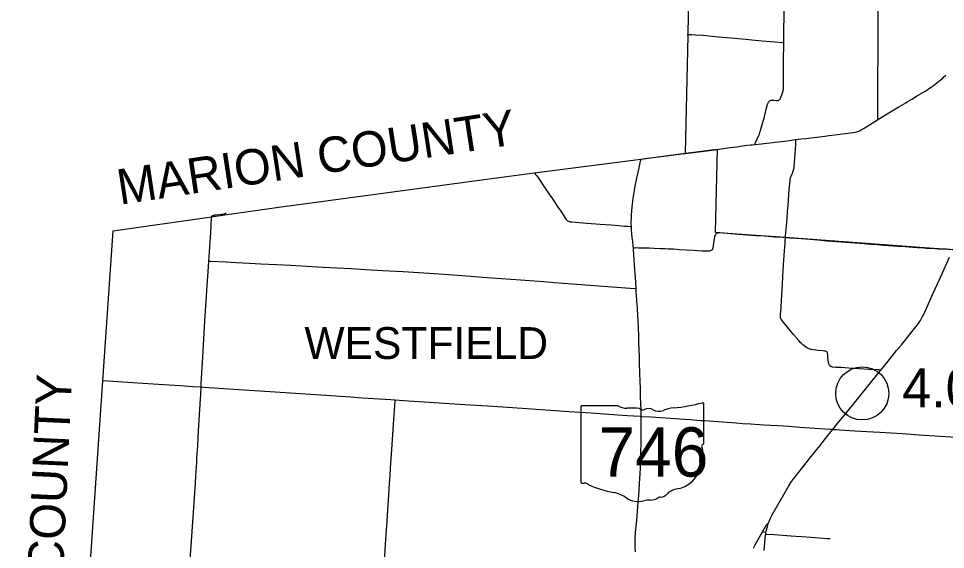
# Model space of a CAD drawing. Extents: x 1815539 to 1947826, y 273303 to 993194.
# Drawn here: x 1822046 to 1848246, y 896327 to 911339 of the extents above; entities that cross this region are included whole.
import ezdxf

# ---------------------------------------------------------------- set-up
doc = ezdxf.new("R2010")
doc.units = 0
for name, color, linetype in [('Default', 7, 'Continuous'), ('GM_X_Adjacent_County_Text', 7, 'Continuous'), ('GM_X_County', 7, 'Continuous'), ('GM_X_County_Road', 7, 'Continuous'), ('GM_X_State_Route', 7, 'Continuous'), ('GM_X_Township', 7, 'Continuous'), ('GM_X_Township_Road', 7, 'Continuous'), ('GM_X_Township_Text', 7, 'Continuous'), ('GM_X_US_Route', 7, 'Continuous'), ('SC_Shading3', 7, 'Continuous')]:
    doc.layers.add(name, color=color, linetype=linetype)

msp = doc.modelspace()

# ---------------------------------------------------------------- linework, layer by layer
at = {"layer": 'Default'}
msp.add_circle((1845895, 900740), 750, dxfattribs=at)
at = {"layer": 'GM_X_County'}
msp.add_lwpolyline([(1824025, 895167), (1824431, 901093), (1824723, 905333), (1827503, 905733), (1827940, 905796), (1829401, 906007), (1835631, 906848), (1836624, 906977), (1839634, 907367), (1840896, 907530), (1840970, 910855), (1841058, 916141)], dxfattribs=at)
at = {"layer": 'GM_X_County_Road'}
for points in [[(1846335, 908486), (1846602, 908646), (1846771, 908747), (1846926, 908839), (1847123, 908956), (1847166, 908980), (1847291, 909058), (1847431, 909144), (1847670, 909287), (1847753, 909339), (1847821, 909386), (1847904, 909446), (1848000, 909518), (1848094, 909595), (1848171, 909657), (1848195, 909678), (1848255, 909735)], [(1844020, 907915), (1844165, 907934), (1844311, 907951), (1844523, 907976), (1844767, 908006), (1844962, 908031), (1845271, 908070), (1845548, 908104), (1845645, 908118), (1845694, 908126), (1845742, 908138), (1845788, 908154), (1845818, 908167), (1845862, 908189), (1845946, 908240), (1846321, 908477), (1846335, 908486)], [(1842859, 907776), (1843042, 907796), (1843433, 907840), (1843709, 907876), (1844020, 907915)], [(1840900, 907526), (1841114, 907551), (1841268, 907569)], [(1841268, 907569), (1841276, 907570), (1841649, 907621), (1841792, 907640)], [(1841792, 907640), (1842086, 907679), (1842248, 907701), (1842361, 907716), (1842507, 907736), (1842637, 907754), (1842734, 907766), (1842783, 907770), (1842859, 907776)], [(1839641, 907367), (1839743, 907381), (1840149, 907433), (1840782, 907511), (1840900, 907526)], [(1836640, 906953), (1836662, 906929), (1836693, 906891), (1836740, 906824), (1836905, 906580), (1837062, 906349), (1837146, 906228), (1837275, 906038), (1837375, 905888), (1837508, 905681), (1837527, 905655), (1837538, 905643), (1837550, 905632), (1837563, 905622), (1837577, 905613), (1837592, 905607), (1837608, 905602), (1837640, 905594), (1837689, 905588), (1837786, 905579), (1838113, 905555), (1838489, 905526), (1838800, 905503), (1839012, 905486), (1839176, 905473), (1839290, 905464), (1839339, 905462), (1839367, 905462)], [(1827427, 904481), (1827436, 904614), (1827477, 905285), (1827502, 905699), (1827503, 905715), (1827505, 905729)], [(1827505, 905729), (1827509, 905742), (1827514, 905753), (1827521, 905760), (1827528, 905766), (1827537, 905772), (1827553, 905778), (1827569, 905783), (1827589, 905785), (1827635, 905791), (1827781, 905804), (1827829, 905810), (1827860, 905815), (1827876, 905820), (1827889, 905826), (1827901, 905834), (1827910, 905844)], [(1839424, 904857), (1839445, 904858), (1839474, 904860), (1839506, 904861), (1839573, 904860), (1839703, 904858), (1839867, 904853), (1840015, 904847), (1840195, 904840), (1840326, 904836), (1840408, 904832), (1840555, 904823), (1840719, 904812), (1841112, 904788), (1841358, 904774), (1841489, 904767), (1841538, 904767), (1841571, 904769), (1841587, 904772), (1841603, 904777), (1841618, 904783), (1841633, 904791), (1841647, 904800), (1841660, 904810), (1841668, 904821), (1841673, 904834), (1841676, 904854), (1841686, 904919), (1841705, 905049), (1841725, 905162), (1841732, 905195), (1841737, 905210), (1841738, 905210)], [(1841738, 905210), (1841744, 905225), (1841753, 905239), (1841764, 905251), (1841776, 905262), (1841790, 905271), (1841804, 905278), (1841820, 905283), (1841836, 905286), (1841869, 905286), (1841984, 905277), (1842180, 905262), (1842393, 905246), (1842884, 905209), (1843129, 905192), (1843424, 905171), (1843653, 905154), (1843723, 905149)], [(1843723, 905149), (1843850, 905140), (1844177, 905115), (1844635, 905078), (1844897, 905058), (1845420, 905017), (1845944, 904974), (1846140, 904960), (1846320, 904946), (1846500, 904933), (1846910, 904905), (1847106, 904892), (1847319, 904877), (1847450, 904869), (1847548, 904862), (1847712, 904849), (1847954, 904835), (1848047, 904830), (1848171, 904827), (1848285, 904823), (1848367, 904817), (1848432, 904810), (1848455, 904806)], [(1827209, 900922), (1827209, 900929), (1827211, 901011), (1827236, 901470), (1827252, 901764), (1827314, 902796), (1827379, 903779), (1827408, 904188), (1827427, 904481)], [(1824436, 901107), (1824857, 901077), (1825561, 901032), (1826298, 900984), (1826625, 900961), (1826969, 900938), (1827209, 900922)], [(1826827, 894987), (1826827, 895001), (1826851, 895345), (1826907, 896163), (1826952, 896835), (1826990, 897375), (1827034, 898063), (1827056, 898390), (1827082, 898783), (1827090, 898914), (1827110, 899258), (1827135, 899684), (1827164, 900142), (1827200, 900716), (1827209, 900922)], [(1827209, 900922), (1827280, 900917), (1827984, 900871), (1829162, 900793), (1830734, 900688), (1831437, 900640), (1831765, 900619), (1832567, 900564), (1832693, 900555)], [(1832693, 900555), (1832927, 900540), (1833221, 900520), (1834662, 900428), (1835464, 900375), (1836413, 900311), (1837608, 900230), (1837903, 900211), (1838230, 900188), (1838983, 900135), (1839261, 900118), (1839621, 900093), (1839646, 900091)], [(1843075, 896824), (1843100, 896869), (1843191, 897024), (1843205, 897042), (1843219, 897058), (1843247, 897084)], [(1842818, 896368), (1842866, 896457), (1843075, 896824)], [(1843075, 896824), (1843090, 896822), (1843154, 896815), (1843172, 896813)]]:
    msp.add_lwpolyline(points, dxfattribs=at)
at = {"layer": 'GM_X_State_Route'}
msp.add_lwpolyline([(1839481, 896262), (1839474, 896409), (1839471, 896524), (1839473, 896606), (1839477, 896688), (1839495, 896901), (1839518, 897146), (1839541, 897407), (1839564, 897668), (1839577, 897848), (1839599, 898192), (1839616, 898470), (1839625, 898634), (1839635, 898896), (1839639, 899093), (1839642, 899306), (1839645, 899552), (1839646, 899879), (1839647, 900076), (1839646, 900091), (1839642, 900273), (1839638, 900437), (1839630, 900666), (1839624, 900879), (1839617, 901092), (1839611, 901305), (1839601, 901617), (1839594, 901797), (1839583, 902158), (1839577, 902371), (1839569, 902600), (1839553, 902944), (1839541, 903140), (1839526, 903369), (1839508, 903631), (1839503, 903706), (1839481, 904024), (1839459, 904367), (1839449, 904514), (1839438, 904662), (1839428, 904809), (1839424, 904857), (1839420, 904907), (1839407, 905037), (1839395, 905151), (1839374, 905363), (1839367, 905462), (1839367, 905469), (1839364, 905527), (1839365, 905610), (1839368, 905692), (1839375, 905790), (1839394, 906002), (1839421, 906263), (1839434, 906361), (1839453, 906474), (1839478, 906603), (1839525, 906828), (1839589, 907116), (1839629, 907309), (1839641, 907367)], dxfattribs=at)
at = {"layer": 'GM_X_Township'}
msp.add_lwpolyline([(1840896, 907530), (1841789, 907648), (1841735, 905294), (1841826, 905293), (1842755, 905225), (1843722, 905154), (1847517, 904873), (1848451, 904813), (1848761, 904780), (1849137, 904752), (1856354, 904189)], dxfattribs=at)
at = {"layer": 'GM_X_Township_Road'}
for points in [[(1843673, 910654), (1843673, 910665), (1843674, 910829), (1843678, 911059), (1843683, 911370), (1843689, 911584), (1843693, 911797), (1843698, 911961), (1843700, 912002)], [(1846335, 908486), (1846333, 908570), (1846332, 908863), (1846331, 909077), (1846333, 909208), (1846337, 909700), (1846338, 909815), (1846342, 910192), (1846344, 910619), (1846342, 910799), (1846342, 910930), (1846343, 911177), (1846343, 911357), (1846343, 911521), (1846347, 911849), (1846351, 911985)], [(1840948, 910890), (1841075, 910891), (1841180, 910883), (1841393, 910865), (1841835, 910824), (1842179, 910791), (1842605, 910753), (1842769, 910737), (1843064, 910710), (1843425, 910677), (1843638, 910658), (1843673, 910654)], [(1842859, 907776), (1842868, 907806), (1842877, 907836), (1842890, 907866), (1842949, 907983), (1842969, 908028), (1842987, 908074), (1843003, 908120), (1843031, 908214), (1843076, 908372), (1843127, 908563), (1843172, 908737), (1843210, 908880), (1843219, 908912), (1843230, 908943), (1843237, 908957), (1843245, 908972), (1843254, 908986), (1843265, 908998), (1843277, 909009), (1843290, 909018), (1843305, 909025), (1843320, 909030), (1843336, 909034), (1843352, 909035), (1843368, 909035), (1843401, 909032), (1843467, 909024), (1843483, 909022), (1843500, 909023), (1843516, 909025), (1843532, 909030), (1843546, 909036), (1843559, 909046), (1843569, 909058), (1843578, 909072), (1843585, 909087), (1843597, 909118), (1843618, 909180), (1843641, 909242), (1843655, 909289), (1843662, 909321), (1843666, 909353), (1843669, 909435), (1843669, 909550), (1843670, 909697), (1843672, 910124), (1843672, 910321), (1843673, 910452), (1843673, 910654)], [(1843723, 905149), (1843725, 905182), (1843727, 905199), (1843758, 905575), (1843781, 905869), (1843797, 906066), (1843832, 906507), (1843845, 906671), (1843853, 906753), (1843861, 906801), (1843869, 906833), (1843884, 906880), (1843920, 906971), (1843943, 907033), (1843957, 907080), (1843967, 907128), (1843974, 907177), (1843980, 907242), (1843990, 907406), (1844004, 907633), (1844015, 907806), (1844019, 907886), (1844020, 907915)], [(1843619, 902807), (1843615, 902812), (1843607, 902826), (1843599, 902840), (1843592, 902855), (1843587, 902870), (1843584, 902886), (1843583, 902903), (1843583, 902919), (1843586, 902969), (1843599, 903165), (1843612, 903378), (1843637, 903821), (1843651, 904050), (1843670, 904378), (1843696, 904771), (1843712, 905001), (1843716, 905060), (1843723, 905149)], [(1827427, 904481), (1827457, 904480), (1827473, 904479), (1827916, 904456), (1828195, 904442), (1828571, 904422), (1828899, 904406), (1829342, 904384), (1829735, 904363), (1830653, 904311), (1831440, 904270), (1831849, 904247), (1832341, 904219), (1832915, 904186), (1833652, 904137), (1834208, 904099), (1834700, 904064), (1835289, 904021), (1836369, 903941), (1836893, 903903), (1837188, 903880), (1837695, 903842), (1838071, 903813), (1839332, 903717), (1839463, 903709), (1839503, 903706)], [(1846415, 901392), (1846377, 901399), (1846361, 901402), (1846328, 901405), (1846082, 901418), (1845803, 901436), (1845508, 901456), (1845295, 901468), (1845148, 901476), (1845066, 901483), (1845050, 901486), (1845034, 901491), (1845019, 901497), (1845004, 901504), (1844991, 901513), (1844979, 901524), (1844968, 901537), (1844959, 901551), (1844953, 901566), (1844948, 901582), (1844942, 901614), (1844924, 901776), (1844921, 901824), (1844916, 901875), (1844912, 901891), (1844905, 901905), (1844893, 901917), (1844879, 901925), (1844863, 901930), (1844831, 901935), (1844782, 901941), (1844651, 901954), (1844520, 901968), (1844472, 901977), (1844440, 901985), (1844409, 901995), (1844378, 902008), (1844349, 902022), (1844320, 902038), (1844279, 902064), (1844238, 902092), (1844213, 902113), (1844177, 902147), (1844143, 902183), (1844100, 902232), (1843953, 902409), (1843783, 902609), (1843646, 902773), (1843619, 902807)], [(1832301, 894618), (1832315, 894864), (1832371, 895683), (1832431, 896616), (1832465, 897124), (1832485, 897452), (1832513, 897861), (1832526, 898058), (1832553, 898418), (1832564, 898631), (1832599, 899155), (1832618, 899433), (1832657, 900006), (1832692, 900530), (1832693, 900555)], [(1839646, 900091), (1839927, 900073), (1840188, 900055), (1840467, 900036), (1840876, 900008), (1841039, 899998), (1841219, 899984), (1841332, 899976)], [(1841332, 899976), (1841432, 899969), (1841562, 899960), (1841955, 899935), (1842326, 899906), (1842505, 899893), (1842735, 899877), (1843111, 899853), (1843504, 899830), (1843667, 899819), (1843814, 899810), (1844125, 899789), (1844976, 899729), (1845025, 899726), (1845066, 899723)], [(1845066, 899723), (1845147, 899721), (1845255, 899713), (1845402, 899702), (1845680, 899685), (1846024, 899665), (1846401, 899642), (1847023, 899602), (1847498, 899572), (1847957, 899544), (1848547, 899506), (1848803, 899489)], [(1843165, 896763), (1843188, 896762), (1843414, 896751), (1843872, 896717), (1844017, 896706), (1844182, 896694), (1844446, 896676), (1844906, 896640), (1844991, 896635)]]:
    msp.add_lwpolyline(points, dxfattribs=at)
at = {"layer": 'GM_X_US_Route'}
msp.add_lwpolyline([(1843124, 896298), (1843150, 896623), (1843162, 896741), (1843165, 896763), (1843168, 896787), (1843172, 896813), (1843176, 896831), (1843187, 896883), (1843221, 897010), (1843238, 897059), (1843247, 897084), (1843261, 897120), (1843272, 897146), (1843301, 897208), (1843352, 897309), (1843538, 897637), (1843676, 897879), (1843814, 898122), (1843876, 898218), (1843963, 898337), (1844453, 898953), (1844699, 899261), (1844922, 899545), (1845066, 899723), (1845189, 899877), (1845436, 900184), (1846097, 901000), (1846376, 901344), (1846415, 901392), (1846627, 901654), (1846866, 901950), (1847000, 902116), (1847258, 902435), (1847412, 902626), (1847481, 902719), (1847513, 902766), (1847536, 902801), (1847576, 902872), (1847605, 902931), (1847649, 903020), (1847899, 903573), (1848122, 904066), (1848357, 904590)], dxfattribs=at)
at = {"layer": 'SC_Shading3'}
for p, q in [((1837940, 900352), (1837940, 898239)), ((1838994, 900388), (1837974, 900388)), ((1841420, 899335), (1841420, 900441)), ((1841420, 899336), (1841420, 899335))]:
    msp.add_line(p, q, dxfattribs=at)
for centre, major_axis, start_param, end_param in [((1837980, 900357), (40.3, 0), 1.712693, 3.28349), ((1839236, 900634), (391, 0), 4.042523, 4.731795), ((1839366, 899202), (1404, 0), 1.404758, 1.657858), ((1839685, 900367), (113, 0), 3.836095, 5.185415), ((1839850, 900123), (235, 0), 0.950623, 2.079405), ((1840153, 900458), (282, 0), 4.081561, 5.145723), ((1840651, 899743), (743, 0), 1.699011, 2.107814), ((1840181, 903270), (3691, 0), 4.814394, 5.042369), ((1841382, 900445), (38.7, 0), 6.141152, 7.989035), ((1841411, 899254), (60, 0), 1.883978, 3.671073), ((1841030, 899114), (360, 0), 5.934695, 6.695948), ((1841379, 899331), (41.5, 0), 5.05454, 6.418171), ((1841559, 898873), (262, 0), 2.387724, 3.262537), ((1840387, 898732), (923, 0), 5.101752, 6.440018), ((1837980, 898234), (40.7, 0), 3.00124, 4.508301), ((1837986, 898450), (310, 0), 4.665946, 4.897461), ((1838050, 898117), (112, 0), 0.519207, 1.627899), ((1839463, 900016), (2665, 0), 4.195997, 4.488961), ((1838668, 897289), (834, 0), 0.823519, 1.323587), ((1840136, 898034), (298, 0), 4.937069, 5.64225), ((1840777, 897645), (506, 0), 1.647645, 2.488434), ((1839570, 898106), (529, 0), 4.026481, 4.996735), ((1839876, 897376), (435, 0), 1.495662, 1.94098), ((1839915, 897948), (282, 0), 4.691044, 5.507374), ((1840170, 897743), (79.4, 0), 1.147584, 2.315152)]:
    msp.add_ellipse(centre, major_axis=major_axis, ratio=0.8, start_param=start_param, end_param=end_param, dxfattribs=at)

# ---------------------------------------------------------------- texts
at = {"layer": 'Default'}
msp.add_text('4.00', height=1100, dxfattribs=at).set_placement((1847025, 900349))
at = {"layer": 'GM_X_Adjacent_County_Text'}
for rotation, p in [(8.6829, (1824911, 906071)), (87.3751, (1823040, 889902))]:
    msp.add_text('MARION COUNTY', height=1000, rotation=rotation, dxfattribs=at).set_placement(p)
at = {"layer": 'GM_X_Township_Text'}
msp.add_text('WESTFIELD', height=900, rotation=0, dxfattribs=at).set_placement((1830126, 901713))
at = {"layer": 'SC_Shading3'}
msp.add_text('746', height=1392.2, dxfattribs=at).set_placement((1838438, 898388))

doc.saveas('drawing.dxf')
